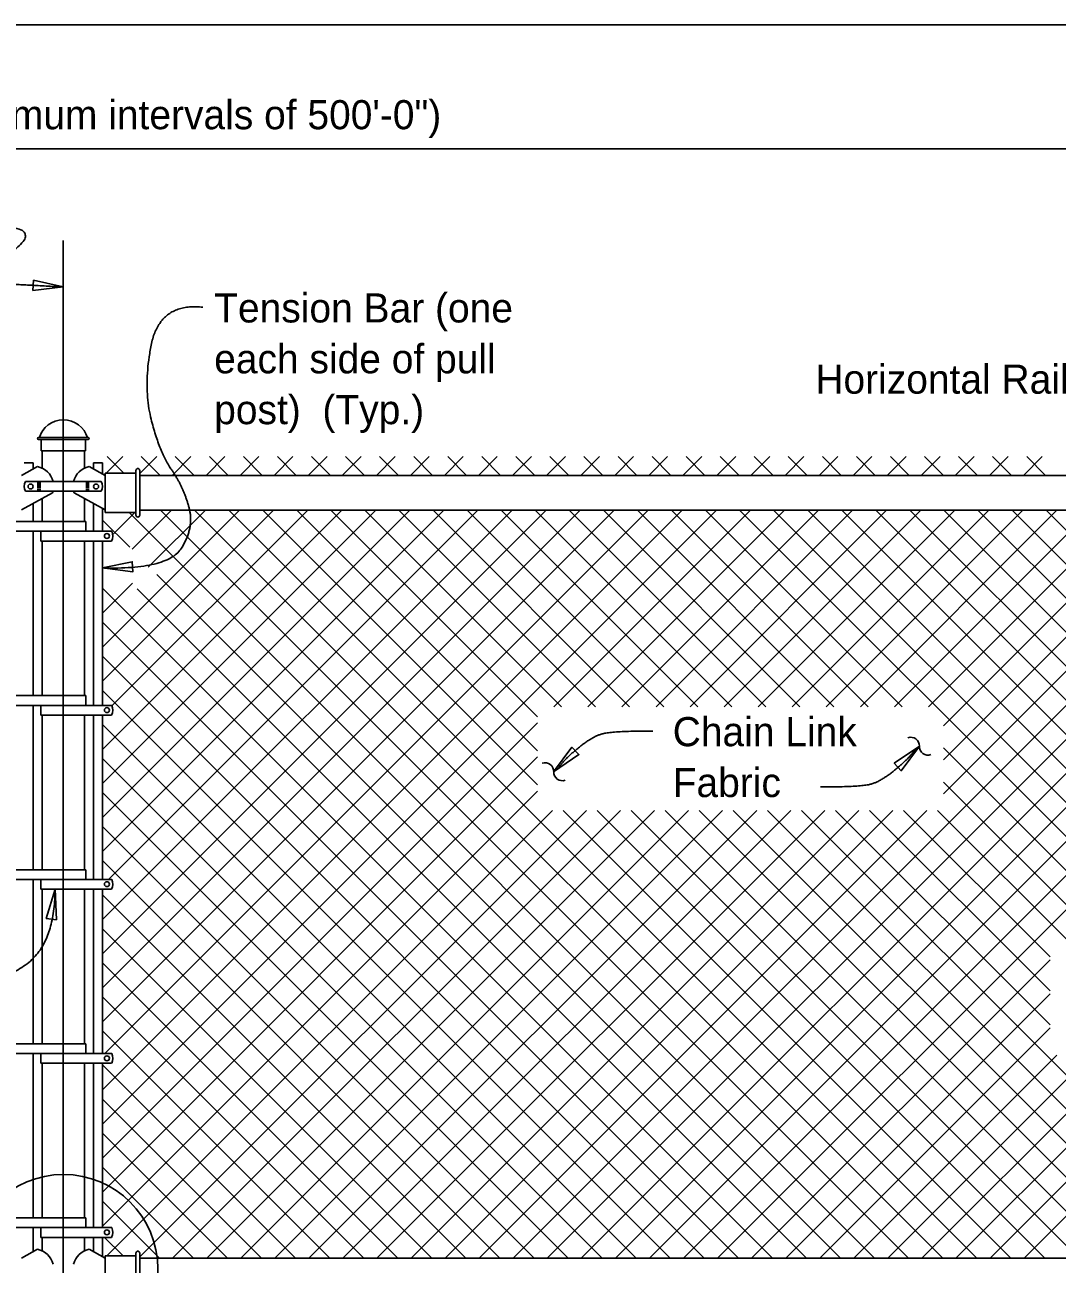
# Model space of a CAD drawing. Extents: x 0 to 41.1, y 0 to 25.9.
# Drawn here: x 11.81 to 18.95, y 17.37 to 25.95 of the extents above; entities that cross this region are included whole.
import ezdxf

# ---------------------------------------------------------------- set-up
doc = ezdxf.new("R2010")
doc.units = 0
for name, color, linetype in [('ActivePts-ConstElements', 7, 'Continuous'), ('CL_Major', 7, 'Continuous'), ('Dimension', 7, 'Continuous'), ('Miscellaneous', 7, 'Continuous'), ('Miscellaneous1', 7, 'Continuous'), ('SteelMisc', 7, 'Continuous'), ('TextStructures', 7, 'Continuous')]:
    doc.layers.add(name, color=color, linetype=linetype)

msp = doc.modelspace()

# ---------------------------------------------------------------- linework, layer by layer
at = {"layer": 'ActivePts-ConstElements'}
msp.add_lwpolyline([(0, 0), (41.0506, 0), (41.0506, 25.9461), (0, 25.9461)], close=True, dxfattribs=at)
at = {"layer": 'CL_Major'}
msp.add_line((12.075, 24.4537), (12.075, 16.5436), dxfattribs=at)
at = {"layer": 'Dimension'}
msp.add_line((2.075, 25.0883), (22.075, 25.0883), dxfattribs=at)
for points in [[(12.075, 24.1318), (11.869, 24.1784), (11.8652, 24.108)], [(12.3459, 22.1868), (12.5554, 22.1599), (12.5526, 22.2304)], [(15.4685, 20.777), (15.6438, 20.8949), (15.5952, 20.946)], [(18.0007, 20.9531), (17.8255, 20.8352), (17.8741, 20.784)], [(12.0179, 19.9637), (11.957, 19.7615), (12.027, 19.7527)]]:
    msp.add_lwpolyline(points, close=True, dxfattribs=at)
msp.add_circle((12.0765, 17.337), 0.6527, dxfattribs=at)
for centre, start, end in [((17.9406, 20.9558), 357.71778, 109.44499), ((18.0597, 20.9511), 177.71778, 289.44499), ((15.4095, 20.7789), 357.71778, 109.44499), ((15.5286, 20.7741), 177.71778, 289.44499)]:
    msp.add_arc(centre, 0.0596, start, end, dxfattribs=at)
for points in [[(11.1855, 24.5555), (11.7313, 24.5653), (11.8537, 24.4764), (11.6095, 24.2951), (11.5247, 24.2768), (11.5247, 24.1589), (11.8027, 24.1466), (12.075, 24.1317)], [(13.0415, 23.9913), (12.7414, 24.0233), (12.626, 23.441), (12.741, 22.9867), (12.9046, 22.7516), (12.9838, 22.4652), (12.7975, 22.1764), (12.3459, 22.1868)], [(16.1538, 21.0586), (15.8636, 21.0586), (15.727, 21.0138), (15.54, 20.8602), (15.5016, 20.8026)], [(17.3154, 20.6713), (17.6056, 20.6713), (17.7422, 20.7161), (17.9292, 20.8697), (17.9676, 20.9273)], [(10.3869, 19.3682), (10.7834, 19.3742), (11.2324, 19.311), (11.5936, 19.2943), (12.0146, 19.5727), (12.0178, 19.9637)]]:
    msp.add_open_spline(points, degree=2, dxfattribs=at)
at = {"layer": 'Miscellaneous'}
for p, q in [((12.3713, 22.8425), (12.486, 22.9573)), ((12.3786, 22.9573), (12.4933, 22.8425)), ((12.6044, 22.8399), (12.7217, 22.9573)), ((12.6143, 22.9573), (12.7444, 22.8271)), ((12.8273, 22.8271), (12.9574, 22.9573)), ((12.85, 22.9573), (12.9801, 22.8271)), ((13.063, 22.8271), (13.1931, 22.9573)), ((13.0857, 22.9573), (13.2158, 22.8271)), ((13.2987, 22.8271), (13.4288, 22.9573)), ((13.3214, 22.9573), (13.4515, 22.8271)), ((13.5344, 22.8271), (13.6645, 22.9573)), ((13.5571, 22.9573), (13.6872, 22.8271)), ((13.7701, 22.8271), (13.9002, 22.9573)), ((13.7928, 22.9573), (13.923, 22.8271)), ((14.0058, 22.8271), (14.1359, 22.9573)), ((14.0285, 22.9573), (14.1587, 22.8271)), ((14.2415, 22.8271), (14.3716, 22.9573)), ((14.2642, 22.9573), (14.3944, 22.8271)), ((14.4772, 22.8271), (14.6073, 22.9573)), ((14.4999, 22.9573), (14.6301, 22.8271)), ((14.7129, 22.8271), (14.843, 22.9573)), ((14.7356, 22.9573), (14.8658, 22.8271)), ((14.9486, 22.8271), (15.0787, 22.9573)), ((14.9713, 22.9573), (15.1015, 22.8271)), ((15.1843, 22.8271), (15.3144, 22.9573)), ((15.207, 22.9573), (15.3372, 22.8271)), ((15.42, 22.8271), (15.5501, 22.9573)), ((15.4427, 22.9573), (15.5729, 22.8271)), ((15.6557, 22.8271), (15.7858, 22.9573)), ((15.6784, 22.9573), (15.8086, 22.8271)), ((15.8914, 22.8271), (16.0215, 22.9573)), ((15.9141, 22.9573), (16.0443, 22.8271)), ((16.1271, 22.8271), (16.2573, 22.9573)), ((16.1498, 22.9573), (16.28, 22.8271)), ((16.3628, 22.8271), (16.493, 22.9573)), ((16.3855, 22.9573), (16.5157, 22.8271)), ((16.5985, 22.8271), (16.7287, 22.9573)), ((16.6212, 22.9573), (16.7514, 22.8271)), ((16.8342, 22.8271), (16.9644, 22.9573)), ((16.8569, 22.9573), (16.9871, 22.8271)), ((17.0699, 22.8271), (17.2001, 22.9573)), ((17.0926, 22.9573), (17.2228, 22.8271)), ((17.3056, 22.8271), (17.4358, 22.9573)), ((17.3283, 22.9573), (17.4585, 22.8271)), ((17.5413, 22.8271), (17.6715, 22.9573)), ((17.564, 22.9573), (17.6942, 22.8271)), ((17.777, 22.8271), (17.9072, 22.9573)), ((17.7997, 22.9573), (17.9299, 22.8271)), ((18.0127, 22.8271), (18.1429, 22.9573)), ((18.0354, 22.9573), (18.1656, 22.8271)), ((18.2484, 22.8271), (18.3786, 22.9573)), ((18.2711, 22.9573), (18.4013, 22.8271)), ((18.4841, 22.8271), (18.6143, 22.9573)), ((18.5068, 22.9573), (18.637, 22.8271)), ((18.7198, 22.8271), (18.85, 22.9573)), ((18.7425, 22.9573), (18.8727, 22.8271)), ((12.3459, 19.5173), (15.4161, 22.5875)), ((12.3459, 19.0459), (15.8875, 22.5875)), ((12.3459, 20.9315), (14.0019, 22.5875)), ((12.3459, 20.4601), (14.4733, 22.5875)), ((12.3459, 21.4029), (13.5305, 22.5875)), ((12.3459, 19.2816), (15.6518, 22.5875)), ((12.3459, 19.753), (15.1804, 22.5875)), ((12.3459, 20.2244), (14.709, 22.5875)), ((12.3459, 20.6958), (14.2376, 22.5875)), ((12.3459, 18.3388), (16.5946, 22.5875)), ((12.3459, 18.5745), (16.3589, 22.5875)), ((12.3459, 21.6386), (13.2948, 22.5875)), ((12.3622, 18.8265), (16.1232, 22.5875)), ((12.3885, 20.0313), (14.9447, 22.5875)), ((12.4117, 21.2331), (13.7662, 22.5875)), ((12.4177, 22.4176), (12.5775, 22.5774)), ((12.5298, 22.5703), (17.6898, 17.4104)), ((12.5524, 22.3165), (12.8234, 22.5875)), ((12.6632, 22.1917), (13.0591, 22.5875)), ((12.7483, 22.5875), (17.9255, 17.4104)), ((12.984, 22.5875), (18.1612, 17.4104)), ((13.2197, 22.5875), (18.3969, 17.4104)), ((13.4554, 22.5875), (15.3576, 20.6854)), ((13.6911, 22.5875), (15.3576, 20.9211)), ((13.9268, 22.5875), (15.3576, 21.1568)), ((14.1625, 22.5875), (15.523, 21.227)), ((14.3982, 22.5875), (15.7587, 21.227)), ((14.6339, 22.5875), (15.9944, 21.227)), ((14.8696, 22.5875), (16.2301, 21.227)), ((15.1053, 22.5875), (16.4658, 21.227)), ((15.1887, 17.4104), (20.3658, 22.5875)), ((15.341, 22.5875), (16.7015, 21.227)), ((15.4244, 17.4104), (20.6015, 22.5875)), ((15.4698, 21.227), (16.8303, 22.5875)), ((15.5767, 22.5875), (16.9372, 21.227)), ((15.6601, 17.4104), (20.8372, 22.5875)), ((15.7055, 21.227), (17.066, 22.5875)), ((15.8124, 22.5875), (17.1729, 21.227)), ((15.8958, 17.4104), (21.073, 22.5875)), ((15.9412, 21.227), (17.3017, 22.5875)), ((16.0482, 22.5875), (17.4086, 21.227)), ((16.1315, 17.4104), (21.3087, 22.5875)), ((16.1769, 21.227), (17.5374, 22.5875)), ((16.2839, 22.5875), (17.6443, 21.227)), ((16.3672, 17.4104), (21.5457, 22.5888)), ((16.4126, 21.227), (17.7731, 22.5875)), ((16.5196, 22.5875), (17.88, 21.227)), ((16.6029, 17.4104), (21.7628, 22.5703)), ((16.6483, 21.227), (18.0088, 22.5875)), ((16.7553, 22.5875), (19.7812, 19.5616)), ((16.884, 21.227), (18.2445, 22.5875)), ((16.991, 22.5875), (20.0169, 19.5616)), ((17.1197, 21.227), (18.4802, 22.5875)), ((17.2267, 22.5875), (20.2526, 19.5616)), ((17.3554, 21.227), (18.7159, 22.5875)), ((17.4624, 22.5875), (20.4883, 19.5616)), ((17.5911, 21.227), (18.9516, 22.5875)), ((17.6981, 22.5875), (20.724, 19.5616)), ((17.8268, 21.227), (19.1873, 22.5875)), ((17.9338, 22.5875), (20.9597, 19.5616)), ((18.0625, 21.227), (19.423, 22.5875)), ((18.1657, 21.0945), (19.6587, 22.5875)), ((18.1657, 20.6231), (20.1301, 22.5875)), ((18.1657, 20.8588), (19.8944, 22.5875)), ((18.1695, 22.5875), (21.1954, 19.5616)), ((18.4052, 22.5875), (21.4311, 19.5616)), ((18.6409, 22.5875), (21.6668, 19.5616)), ((18.8766, 22.5875), (21.9292, 19.5349)), ((12.3459, 22.5185), (12.5344, 22.33)), ((12.7225, 22.1419), (17.4541, 17.4104)), ((12.3459, 21.8743), (12.5527, 22.0811)), ((12.3459, 22.0471), (16.9826, 17.4104)), ((12.5855, 22.0432), (17.2183, 17.4104)), ((12.3459, 21.8114), (16.7469, 17.4104)), ((12.3459, 21.5757), (16.5112, 17.4104)), ((12.3459, 21.34), (16.2755, 17.4104)), ((12.3459, 18.1031), (15.3576, 21.1148)), ((12.3459, 21.1043), (16.0398, 17.4104)), ((18.1657, 20.9414), (19.5454, 19.5616)), ((12.3459, 17.8674), (15.3576, 20.8791)), ((12.3459, 20.8686), (15.8041, 17.4104)), ((18.1657, 20.7057), (19.3097, 19.5616)), ((12.3459, 17.6317), (15.3576, 20.6434)), ((12.3459, 20.6329), (15.5684, 17.4104)), ((12.3757, 17.4258), (15.4595, 20.5096)), ((12.6044, 17.4187), (15.6952, 20.5096)), ((12.8317, 17.4104), (15.931, 20.5096)), ((13.0674, 17.4104), (16.1667, 20.5096)), ((13.3031, 17.4104), (16.4024, 20.5096)), ((13.5388, 17.4104), (16.6381, 20.5096)), ((13.7745, 17.4104), (16.8738, 20.5096)), ((14.0102, 17.4104), (17.1095, 20.5096)), ((14.2459, 17.4104), (17.3452, 20.5096)), ((14.4816, 17.4104), (17.5809, 20.5096)), ((14.7173, 17.4104), (17.8166, 20.5096)), ((14.953, 17.4104), (18.0523, 20.5096)), ((15.5333, 20.5096), (18.6326, 17.4104)), ((15.769, 20.5096), (18.8683, 17.4104)), ((16.0047, 20.5096), (19.104, 17.4104)), ((16.2404, 20.5096), (19.3397, 17.4104)), ((16.4761, 20.5096), (19.5754, 17.4104)), ((16.7118, 20.5096), (19.8111, 17.4104)), ((16.9475, 20.5096), (20.0468, 17.4104)), ((17.1832, 20.5096), (20.2825, 17.4104)), ((17.4189, 20.5096), (18.9042, 19.0243)), ((17.6546, 20.5096), (18.9042, 19.26)), ((17.8903, 20.5096), (18.9042, 19.4957)), ((18.126, 20.5096), (19.074, 19.5616)), ((12.3459, 20.3972), (15.3327, 17.4104)), ((12.3459, 20.1615), (15.097, 17.4104)), ((12.3459, 19.9258), (14.8613, 17.4104)), ((12.3459, 19.6901), (14.6256, 17.4104)), ((16.8386, 17.4104), (18.9042, 19.476)), ((12.3459, 19.4544), (14.3899, 17.4104)), ((12.3459, 19.2187), (14.1542, 17.4104)), ((17.0743, 17.4104), (18.9042, 19.2403)), ((12.3459, 18.983), (13.9185, 17.4104)), ((17.31, 17.4104), (18.9042, 19.0046)), ((17.5457, 17.4104), (18.9514, 18.8161)), ((17.7814, 17.4104), (19.1871, 18.8161)), ((18.0171, 17.4104), (19.4228, 18.8161)), ((18.2528, 17.4104), (19.6585, 18.8161)), ((18.4885, 17.4104), (19.8942, 18.8161)), ((18.7242, 17.4104), (20.1299, 18.8161)), ((12.3459, 18.7473), (13.6828, 17.4104)), ((12.3459, 18.5116), (13.4471, 17.4104)), ((12.3459, 18.2759), (13.2114, 17.4104)), ((12.3459, 18.0402), (12.9757, 17.4104)), ((12.3459, 17.8045), (12.74, 17.4104)), ((12.3605, 17.5542), (12.4889, 17.4258))]:
    msp.add_line(p, q, dxfattribs=at)
at = {"layer": 'Miscellaneous1'}
msp.add_lwpolyline([(0, 25.9461), (41.0506, 25.9461), (41.0506, 0), (0, 0)], close=True, dxfattribs=at)
at = {"layer": 'SteelMisc'}
for p, q in [((11.9028, 23.0892), (12.2473, 23.0892)), ((12.2473, 23.077), (11.9028, 23.077)), ((11.921, 22.9972), (11.921, 23.077)), ((12.2291, 22.9972), (12.2291, 23.077)), ((12.2291, 22.9972), (11.921, 22.9972)), ((11.9292, 22.8773), (11.9292, 22.9972)), ((12.2209, 22.8773), (12.2209, 22.9972)), ((11.8667, 22.9156), (11.8042, 22.9156)), ((11.8667, 22.8727), (11.8667, 22.9156)), ((12.2834, 22.8739), (12.2834, 22.9156)), ((12.2834, 22.9156), (12.3459, 22.9156)), ((12.3459, 22.8381), (12.3459, 22.9156)), ((11.7855, 22.8278), (11.8963, 22.8892)), ((12.3646, 22.8278), (12.2537, 22.8892)), ((12.3646, 22.8425), (12.3646, 22.5703)), ((12.3646, 22.8425), (12.5775, 22.8425)), ((12.5775, 22.8621), (12.5775, 22.5524)), ((12.6044, 22.8621), (12.6044, 22.5524)), ((21.5457, 22.8271), (12.6044, 22.8271)), ((12.3374, 22.7852), (11.8126, 22.7852)), ((11.895, 22.7774), (11.9185, 22.7774)), ((11.895, 22.7678), (11.9185, 22.7678)), ((11.895, 22.757), (11.9185, 22.757)), ((11.895, 22.7452), (11.9185, 22.7452)), ((11.895, 22.7334), (11.9185, 22.7334)), ((12.255, 22.7774), (12.2316, 22.7774)), ((12.255, 22.7678), (12.2316, 22.7678)), ((12.255, 22.757), (12.2316, 22.757)), ((12.255, 22.7452), (12.2316, 22.7452)), ((12.255, 22.7334), (12.2316, 22.7334)), ((11.7855, 22.5884), (11.9994, 22.707)), ((12.3374, 22.7174), (11.8126, 22.7174)), ((11.895, 22.7236), (11.9185, 22.7236)), ((11.9292, 22.5083), (11.9292, 22.6681)), ((12.3646, 22.5884), (12.1506, 22.707)), ((12.2209, 22.5083), (12.2209, 22.668)), ((12.255, 22.7236), (12.2316, 22.7236)), ((11.8667, 22.6334), (11.8667, 22.5083)), ((12.2834, 22.6334), (12.2834, 22.4407)), ((12.2834, 22.6334), (12.2834, 22.5865)), ((12.3459, 22.5987), (12.3459, 22.4407)), ((12.3459, 22.5987), (12.3459, 22.5865)), ((12.5775, 22.5703), (12.3646, 22.5703)), ((21.5457, 22.5875), (12.6044, 22.5875)), ((12.2309, 22.5083), (11.7397, 22.5083)), ((12.2309, 22.5083), (12.2309, 22.4407)), ((12.2309, 22.4407), (11.7405, 22.4407)), ((11.8667, 21.3036), (11.8667, 22.4407)), ((11.9193, 22.4407), (11.9193, 22.3731)), ((11.9193, 22.4407), (12.4104, 22.4407)), ((11.9193, 22.3731), (12.4096, 22.3731)), ((11.9292, 21.3036), (11.9292, 22.3731)), ((12.2209, 21.3036), (12.2209, 22.3731)), ((12.2834, 21.236), (12.2834, 22.3731)), ((12.3459, 21.236), (12.3459, 22.3731)), ((12.2309, 21.3036), (11.7397, 21.3036)), ((12.2309, 21.3036), (12.2309, 21.236)), ((12.2309, 21.236), (11.7405, 21.236)), ((11.8667, 20.0989), (11.8667, 21.236)), ((11.9193, 21.236), (11.9193, 21.1684)), ((11.9193, 21.236), (12.4104, 21.236)), ((11.9193, 21.1684), (12.4096, 21.1684)), ((11.9292, 20.0989), (11.9292, 21.1684)), ((12.2209, 20.0989), (12.2209, 21.1684)), ((12.2834, 20.0313), (12.2834, 21.1684)), ((12.3459, 20.0313), (12.3459, 21.1684)), ((12.2309, 20.0989), (11.7397, 20.0989)), ((12.2309, 20.0989), (12.2309, 20.0313)), ((12.2309, 20.0313), (11.7405, 20.0313)), ((11.8667, 18.8942), (11.8667, 20.0313)), ((11.9193, 20.0313), (11.9193, 19.9637)), ((11.9193, 20.0313), (12.4104, 20.0313)), ((11.9193, 19.9637), (12.4096, 19.9637)), ((11.9292, 18.8942), (11.9292, 19.9637)), ((12.2209, 18.8942), (12.2209, 19.9637)), ((12.2834, 18.8265), (12.2834, 19.9637)), ((12.3459, 18.8265), (12.3459, 19.9637)), ((12.2309, 18.8942), (11.7397, 18.8942)), ((12.2309, 18.8942), (12.2309, 18.8265)), ((12.2309, 18.8265), (11.7405, 18.8265)), ((11.8667, 17.6895), (11.8667, 18.8265)), ((11.9193, 18.8265), (11.9193, 18.7589)), ((11.9193, 18.8265), (12.4104, 18.8265)), ((11.9193, 18.7589), (12.4096, 18.7589)), ((11.9292, 17.6895), (11.9292, 18.7589)), ((12.2209, 17.6895), (12.2209, 18.7589)), ((12.2834, 17.6219), (12.2834, 18.7589)), ((12.3459, 17.6219), (12.3459, 18.7589)), ((12.2309, 17.6895), (11.7397, 17.6895)), ((12.2309, 17.6895), (12.2309, 17.6219)), ((12.2309, 17.6219), (11.7405, 17.6219)), ((11.8667, 17.6219), (11.8667, 17.456)), ((11.9193, 17.6219), (11.9193, 17.5542)), ((11.9193, 17.6219), (12.4104, 17.6219)), ((11.9193, 17.5542), (12.4096, 17.5542)), ((11.9292, 17.4606), (11.9292, 17.5542)), ((12.2209, 17.4606), (12.2209, 17.5542)), ((12.2834, 17.5542), (12.2834, 17.456)), ((12.3459, 17.4214), (12.3459, 17.5542)), ((11.7855, 17.4111), (11.8963, 17.4724)), ((12.3646, 17.4111), (12.2537, 17.4724)), ((12.3646, 17.4258), (12.3646, 17.1536)), ((12.3646, 17.4258), (12.5775, 17.4258)), ((12.5775, 17.4454), (12.5775, 17.1357)), ((12.6044, 17.4454), (12.6044, 17.1357)), ((21.5457, 17.4104), (12.6044, 17.4104))]:
    msp.add_line(p, q, dxfattribs=at)
for centre, radius, start, end in [((11.9029, 23.0829), 0.00613, 91.1647, 268.8353), ((12.2472, 23.0829), 0.00613, 271.1647, 88.8353), ((12.5909, 22.862), 0.0134, 0, 180), ((12.5909, 22.5522), 0.0134, 180, 0), ((12.5909, 17.4453), 0.0134, 0, 180)]:
    msp.add_arc(centre, radius, start, end, dxfattribs=at)
for centre, major_axis, start_param, end_param in [((12.0757, 23.0482), (0.1711, 0), 0.252602, 2.888574), ((11.8618, 22.7532), (0.146, 0), 0.231126, 1.331255), ((12.2882, 22.7532), (-0.146, 0), 4.95193, 6.05206), ((11.8818, 22.7512), (-0.0776, 0), 5.810211, 6.75616), ((12.2683, 22.7512), (0.0776, 0), 5.810211, 6.75616), ((11.8618, 22.7532), (0.146, 0), 5.947976, 6.024627), ((12.2882, 22.7532), (-0.146, 0), 0.258558, 0.335209), ((12.3408, 22.4076), (0.0776, 0), 5.801244, 6.745158), ((12.3408, 21.2029), (0.0776, 0), 5.801046, 6.744962), ((12.3408, 21.2029), (0.0776, 0), 5.801046, 6.744962), ((12.3408, 19.9982), (0.0776, 0), 5.800848, 6.744767), ((12.3408, 19.9982), (0.0776, 0), 5.800848, 6.744767), ((12.3408, 18.7933), (0.0776, 0), 5.810211, 6.745158), ((12.3408, 18.7933), (0.0776, 0), 5.810211, 6.745158), ((12.3408, 17.5887), (0.0776, 0), 5.800651, 6.745353), ((11.8618, 17.3365), (0.146, 0), 0.231126, 1.331255), ((12.2882, 17.3365), (-0.146, 0), 4.95193, 6.05206)]:
    msp.add_ellipse(centre, major_axis=major_axis, ratio=0.957868, start_param=start_param, end_param=end_param, dxfattribs=at)
for centre, major_axis in [((11.8485, 22.7508), (0.0178, 0)), ((12.3016, 22.7508), (-0.0178, 0)), ((12.3767, 22.408), (-0.0177, 0)), ((12.3767, 21.2033), (-0.0177, 0)), ((12.3767, 21.2033), (-0.0177, 0)), ((12.3767, 19.9986), (-0.0177, 0)), ((12.3767, 19.9986), (-0.0177, 0)), ((12.3767, 18.7937), (-0.0177, 0)), ((12.3767, 18.7937), (-0.0177, 0)), ((12.3767, 17.5891), (-0.0177, 0))]:
    msp.add_ellipse(centre, major_axis=major_axis, ratio=0.957868, dxfattribs=at)

# ---------------------------------------------------------------- texts
at = {"layer": 'Dimension'}
for s, p in [('Tension Bar (one ', (13.1191, 23.886)), ('each side of pull ', (13.1191, 23.534)), ('post)  (Typ.)', (13.1191, 23.182)), ('Chain Link ', (16.2925, 20.9534)), ('Fabric ', (16.2925, 20.6014))]:
    msp.add_text(s, height=0.2016, dxfattribs=at).set_placement(p)
at = {"layer": 'TextStructures'}
for s, p in [('Pull Post Assembly (required at maximum intervals of 500\'-0")', (7.3071, 25.2232)), ('Horizontal Rail', (17.2797, 23.3931))]:
    msp.add_text(s, height=0.2016, dxfattribs=at).set_placement(p)

doc.saveas('drawing.dxf')
